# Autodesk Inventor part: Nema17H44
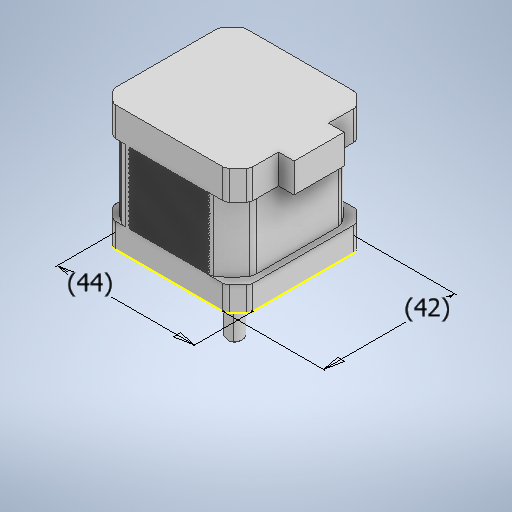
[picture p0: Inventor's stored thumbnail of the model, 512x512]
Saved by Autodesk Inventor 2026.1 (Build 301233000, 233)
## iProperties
Created: 2025-12
Part Number: Nema17H44
Material: Типовые
Document SubType Name: Modeling
Designer: Yury Melnikov
Density: 1 g/cm^3
Appearance: По умолчанию
Author: Yury Melnikov
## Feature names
1. Выдавливание1 [Extrusion]
2. Выдавливание2 [Extrusion]
3. Выдавливание3 [Extrusion]
4. Сопряжение2 [Fillet]
5. Сдвиг1
6. Круговой массив1 [Circular Pattern]
7. Выдавливание4 [Extrusion]
8. Сопряжение3 [Fillet]
9. Выдавливание5 [Extrusion]
10. Фаска2 [Chamfer]
11. Выдавливание6 [Extrusion]
12. Выдавливание7 [Extrusion]
13. Выдавливание8 [Extrusion]
14. Фаска3 [Chamfer]
15. Выдавливание13 [Extrusion]
16. Выдавливание14 [Extrusion]
17. Выдавливание15 [Extrusion]
18. Выдавливание16 [Extrusion]
19. Выдавливание17 [Extrusion]
20. Сопряжение4 [Fillet]
21. Выдавливание18 [Extrusion]
22. Выдавливание19 [Extrusion]
23. Фаска6 [Chamfer]
24. Сопряжение5 [Fillet]
25. Выдавливание20 [Extrusion]
26. Выдавливание23 [Extrusion]
27. Зеркальное отражение2 [Mirror]
28. Выдавливание24 [Extrusion]
29. Выдавливание25 [Extrusion]
## Parameters: d0 = 44 mm, d1 = 42 mm, d2 = 4 mm, d3 = 4 mm, d4 = 4 mm, d5 = 4 mm, d6 = 4 mm, d7 = 4 mm, d8 = 4 mm, d9 = 4 mm, d10 = 2 mm, d11 = 9.4 mm, d12 = 0, d14 = 42 mm, d15 = 7 mm, d16 = 7 mm, d17 = 7 mm, d18 = 7 mm, d19 = 7 mm, d20 = 7 mm, d21 = 7 mm, d22 = 7 mm, d26 = 360 deg, d28 = 22.9 mm, d29 = 0, d30 = 7.8 mm, d31 = 0, d32 = 3 mm, d35 = 0.229 mm, d38 = 0.458 mm, d43 = -11.5 mm, d44 = -15.75 mm, d45 = 0, d46 = 0, d48 = 360 deg, d50 = 22 mm, d51 = 1.9 mm, d52 = 0, d53 = 1 mm, d54 = 9 mm, d55 = 5 mm, d57 = 26.3 mm, d58 = 0, d62 = 0.6 mm, d63 = 2 mm, d64 = 45 deg, d65 = 4.4 mm, d66 = 22.1 mm, d67 = 0, d68 = 5 mm, d69 = 16 mm, d70 = 22.1 mm, d71 = 0, d74 = 30.5 mm, d77 = 30.5 mm, d80 = 2.6 mm, d82 = 0, d83 = 0.6 mm, d84 = 2 mm, d85 = 45 deg, d101 = 3 mm, d102 = 3 mm, d103 = 0, d105 = 0.4 mm, d106 = 3 mm, d107 = 0, d108 = 7 mm, d109 = 37.25 mm, d110 = 0, d113 = 3 mm, d114 = 0, d116 = 0, d117 = 4 mm, d118 = 3 mm, d119 = 3 mm, d120 = 1.75 mm, d123 = 30.5 mm, d126 = 30.5 mm, d130 = 0, d132 = 8 mm, d133 = 4 mm, d134 = 23 mm, d136 = 0, d143 = 12 mm, d144 = 3.2 mm, d145 = 8 mm, d146 = 2 mm, d147 = 45 deg, d148 = 5 mm, d149 = 16.227 mm, d150 = 4.625 mm, d152 = 0, d159 = 3 mm, d161 = 3 mm, d162 = 232 mm, d163 = 4 mm, d164 = 0, d165 = 45 deg, d166 = 3 mm, d167 = 3 mm, d168 = 2 mm, d169 = 0, d170 = 1 mm, d171 = 0, d172 = 42 mm, d173 = 44 mm
